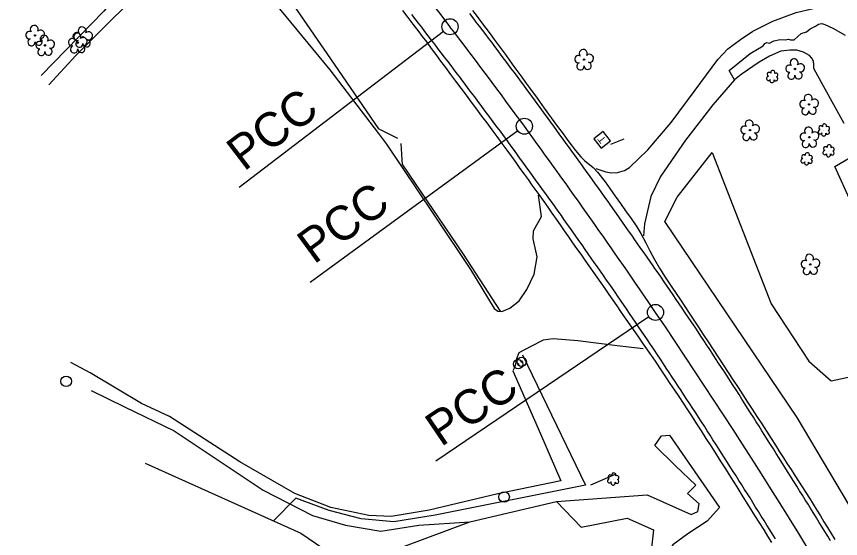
# Model space of a CAD drawing. Extents: x 474972 to 479313, y 498315 to 502691.
# Drawn here: x 477234.5 to 477618.9, y 499710.1 to 499953.8 of the extents above; entities that cross this region are included whole.
import ezdxf

# ---------------------------------------------------------------- set-up
doc = ezdxf.new("R2010")
doc.units = 0
for name, color, linetype in [('Exist Horizontal Alignment', 7, 'Continuous'), ('Exist Other Culture Fence Line', 7, 'Continuous'), ('Exist Other Culture Gate', 7, 'Continuous'), ('Exist Other Culture Sign', 7, 'Continuous'), ('Exist Roads EOP', 7, 'Continuous'), ('Exist Roads EOP Other', 7, 'Continuous'), ('Exist Roads EOT', 7, 'Continuous'), ('Exist Roads Soil', 7, 'Continuous'), ('Exist Utilities Other Located Object CELL', 7, 'Continuous'), ('Exist Utilities Other Pole CELL', 7, 'Continuous'), ('Exist Utilities Telephone Pedestal CELL', 7, 'Continuous'), ('Exist Vegetation Hedge Row', 7, 'Continuous'), ('Exist Vegetation Shrub CELL', 7, 'Continuous'), ('Exist Vegetation Tree CELL', 7, 'Continuous'), ('Exist Vegetation Woods Line', 7, 'Continuous')]:
    doc.layers.add(name, color=color, linetype=linetype)

msp = doc.modelspace()

# ---------------------------------------------------------------- linework, layer by layer
at = {"layer": 'Exist Horizontal Alignment'}
for p, q in [((477433.72, 499946.76), (477338.28, 499873.96)), ((477468.35, 499900.35), (477371.41, 499829.57)), ((477529.46, 499813.56), (477430.14, 499746.15))]:
    msp.add_line(p, q, dxfattribs=at)
for centre in [(477436.7, 499949.03), (477471.38, 499902.56), (477532.56, 499815.66)]:
    msp.add_circle(centre, 3.75, dxfattribs=at)
for centre, radius, start, end in [((475159.06, 498211.82), 2864.54, 37.33366, 48.4381), ((475236.75, 498271.08), 2766.82, 36.13278, 37.33366), ((474971.71, 498077.57), 3094.99, 34.16531, 36.13278), ((475221.34, 498247), 2793.29, 28.78535, 34.16531)]:
    msp.add_arc(centre, radius, start, end, dxfattribs=at)
at = {"layer": 'Exist Other Culture Fence Line'}
for points in [[(477252.46, 499976.08), (477320.07, 500023.97), (477331.36, 500006.71), (477363.76, 499959.01), (477380.88, 499934.01), (477403.42, 499901.35)], [(477414.47, 499884.47), (477442.82, 499842.83), (477460.07, 499816.31)], [(477470.47, 499795.88), (477499.9, 499734.95), (477429.75, 499721.06), (477410.53, 499717.94), (477395.31, 499719.29), (477380.34, 499723.11), (477364.85, 499728.91), (477354.49, 499718.55)]]:
    msp.add_lwpolyline(points, dxfattribs=at)
at = {"layer": 'Exist Other Culture Gate'}
for p, q in [((477412.43, 499896.8), (477403.42, 499901.35)), ((477414.47, 499884.47), (477413.91, 499894.54))]:
    msp.add_line(p, q, dxfattribs=at)
at = {"layer": 'Exist Other Culture Sign'}
for p, q in [((477517.81, 499896.46), (477511.5, 499894.03)), ((477502.37, 499735.15), (477513.9, 499740.16))]:
    msp.add_line(p, q, dxfattribs=at)
at = {"layer": 'Exist Roads EOP'}
for points in [[(477586.86, 499708.28), (477584.99, 499711.26), (477583.17, 499714.15), (477581.22, 499717.25), (477578.96, 499720.85), (477576.39, 499724.96), (477573.51, 499729.56), (477570.58, 499734.26), (477567.84, 499738.62), (477565.3, 499742.66), (477562.95, 499746.36), (477560.7, 499749.89), (477558.48, 499753.39), (477556.26, 499756.85), (477554.07, 499760.3), (477551.9, 499763.68), (477549.76, 499766.97), (477547.66, 499770.18), (477545.6, 499773.29), (477543.55, 499776.37), (477541.51, 499779.43), (477539.47, 499782.49), (477537.44, 499785.54), (477535.54, 499788.39), (477532.5, 499792.86), (477530.34, 499795.94), (477526.98, 499800.84), (477524.41, 499804.6), (477521.45, 499808.84), (477518.17, 499813.55), (477516.42, 499816.07), (477514.61, 499818.7), (477512.76, 499821.38), (477510.9, 499824.07), (477509.03, 499826.75), (477507.16, 499829.43), (477505.29, 499832.11), (477503.41, 499834.78), (477501.54, 499837.45), (477499.68, 499840.11), (477497.81, 499842.78), (477495.92, 499845.48), (477494.02, 499848.21), (477492.1, 499850.96), (477490.17, 499853.72), (477488.25, 499856.49), (477486.32, 499859.25), (477484.38, 499862.01), (477482.47, 499864.74), (477480.58, 499867.41), (477478.73, 499870.02), (477476.92, 499872.57), (477475.1, 499875.11), (477473.26, 499877.67), (477471.4, 499880.26), (477469.5, 499882.88), (477467.54, 499885.59), (477465.47, 499888.43), (477463.31, 499891.41), (477461.04, 499894.54), (477458.71, 499897.73), (477456.36, 499900.93), (477454, 499904.13), (477451.62, 499907.33), (477449.22, 499910.54), (477446.8, 499913.77), (477444.36, 499917.03), (477441.89, 499920.32), (477439.45, 499923.58), (477437.07, 499926.78), (477434.75, 499929.92), (477432.49, 499933), (477430.28, 499936), (477428.12, 499938.92), (477425.99, 499941.76), (477423.9, 499944.52), (477421.78, 499947.3), (477419.53, 499950.23), (477417.16, 499953.31), (477414.67, 499956.52)], [(477447.24, 499956.62), (477449.38, 499953.78), (477451.45, 499951.01), (477453.44, 499948.33), (477455.39, 499945.71), (477457.3, 499943.12), (477459.17, 499940.57), (477461.01, 499938.04), (477462.84, 499935.53), (477464.67, 499933.02), (477466.5, 499930.5), (477468.33, 499927.97), (477470.16, 499925.46), (477471.97, 499922.98), (477473.77, 499920.52), (477477.29, 499915.69), (477480.7, 499910.98), (477483.96, 499906.44), (477486.89, 499902.41), (477489.47, 499898.94), (477491.73, 499895.94), (477495.29, 499891.29), (477497.67, 499888.34), (477499.41, 499886.5), (477503.49, 499883.23), (477505.48, 499881.19), (477509.04, 499876.68), (477511.3, 499873.54), (477513.77, 499869.96), (477516.21, 499866.47), (477518.62, 499863.09), (477521.19, 499859.43), (477523.84, 499855.56), (477525.78, 499852.45), (477527.99, 499848.15), (477529.92, 499844.42), (477532.04, 499840.38), (477534.42, 499836.24), (477537.05, 499832.18), (477540.24, 499827.39), (477542.17, 499824.5), (477544.15, 499821.53), (477546.19, 499818.46), (477548.29, 499815.32), (477550.43, 499812.08), (477552.62, 499808.76), (477554.87, 499805.34), (477557.15, 499801.84), (477559.47, 499798.29), (477561.8, 499794.73), (477564.14, 499791.17), (477566.49, 499787.6), (477568.82, 499784.06), (477571.1, 499780.58), (477573.34, 499777.15), (477575.53, 499773.78), (477577.71, 499770.42), (477579.9, 499767.03), (477582.1, 499763.61), (477584.31, 499760.17), (477586.48, 499756.8), (477588.53, 499753.6), (477590.46, 499750.58), (477592.29, 499747.74), (477594.04, 499744.99), (477595.78, 499742.28), (477597.51, 499739.59), (477599.22, 499736.92), (477600.92, 499734.26), (477602.63, 499731.57), (477604.34, 499728.86), (477606.06, 499726.13), (477607.77, 499723.38), (477609.46, 499720.65), (477611.13, 499717.92), (477612.79, 499715.2), (477614.46, 499712.45), (477616.18, 499709.63)]]:
    msp.add_lwpolyline(points, dxfattribs=at)
at = {"layer": 'Exist Roads EOP Other'}
for points in [[(477620.56, 499903.88), (477611, 499921.25), (477606.36, 499929.49), (477606.41, 499931.2), (477606.25, 499932.98), (477605.51, 499934.39), (477604.46, 499935.51), (477601.65, 499937.12), (477598.41, 499938.06), (477595.23, 499938.13), (477591.05, 499937.62), (477585.71, 499935.21), (477580.96, 499932.41), (477572.48, 499926.7), (477569.34, 499924.21), (477566.9, 499928.64), (477576.74, 499936.48), (477582.82, 499940.05), (477583.57, 499941.25), (477584.55, 499941.7), (477585.79, 499941.35), (477587.79, 499942.39), (477590.78, 499943.08), (477593.09, 499942.85), (477594.55, 499943.21), (477595.57, 499942.83), (477597.2, 499942.85), (477598.93, 499944.46), (477600.52, 499945.81), (477603.01, 499946.64), (477604.78, 499948.04), (477607.27, 499949.32), (477608.65, 499950.18), (477610.17, 499950.53), (477611.61, 499950.08), (477615.29, 499948.29), (477620.99, 499945.06)], [(477623.82, 499866.98), (477616.17, 499883.71), (477627.93, 499890.55)]]:
    msp.add_lwpolyline(points, dxfattribs=at)
at = {"layer": 'Exist Roads EOT'}
for points in [[(477614.25, 499709.07), (477612.93, 499711.2), (477611.61, 499713.32), (477610.29, 499715.44), (477608.98, 499717.57), (477607.66, 499719.69), (477606.34, 499721.81), (477605.02, 499723.94), (477603.71, 499726.06), (477602.39, 499728.18), (477601.07, 499730.3), (477599.75, 499732.43), (477598.43, 499734.55), (477597.12, 499736.67), (477596.85, 499737.11), (477595.52, 499739.22), (477594.19, 499741.34), (477592.85, 499743.45), (477591.52, 499745.56), (477590.19, 499747.68), (477588.86, 499749.79), (477587.53, 499751.91), (477586.2, 499754.02), (477584.87, 499756.14), (477583.54, 499758.25), (477582.21, 499760.37), (477580.87, 499762.48), (477579.54, 499764.6), (477578.21, 499766.71), (477576.88, 499768.83), (477575.55, 499770.94), (477574.22, 499773.05), (477572.89, 499775.17), (477571.56, 499777.28), (477570.17, 499779.48), (477568.81, 499781.57), (477567.44, 499783.66), (477566.07, 499785.75), (477564.7, 499787.84), (477563.33, 499789.93), (477561.97, 499792.02), (477560.6, 499794.11), (477559.23, 499796.21), (477557.86, 499798.3), (477556.49, 499800.39), (477555.13, 499802.48), (477553.76, 499804.57), (477552.39, 499806.66), (477551.02, 499808.75), (477550.64, 499809.34), (477549.23, 499811.4), (477547.82, 499813.47), (477546.41, 499815.53), (477545, 499817.59), (477543.59, 499819.66), (477542.18, 499821.72), (477540.77, 499823.78), (477539.36, 499825.85), (477537.95, 499827.91), (477536.54, 499829.97), (477535.14, 499832.04), (477533.73, 499834.1), (477532.32, 499836.16), (477531.51, 499837.34), (477530.08, 499839.38), (477528.64, 499841.43), (477527.21, 499843.48), (477525.77, 499845.52), (477524.34, 499847.57), (477522.9, 499849.61), (477521.47, 499851.66), (477520.03, 499853.7), (477518.6, 499855.75), (477517.16, 499857.8), (477515.73, 499859.84), (477514.29, 499861.89), (477512.86, 499863.93), (477511.42, 499865.98), (477510.44, 499867.38), (477508.99, 499869.41), (477507.53, 499871.44), (477506.08, 499873.48), (477504.62, 499875.51), (477503.17, 499877.54), (477501.72, 499879.57), (477500.26, 499881.6), (477498.81, 499883.64), (477497.35, 499885.67), (477496.8, 499886.44), (477495.34, 499888.46), (477493.87, 499890.49), (477492.4, 499892.51), (477490.93, 499894.53), (477489.47, 499896.55), (477488, 499898.58), (477486.53, 499900.6), (477485.06, 499902.62), (477483.6, 499904.64), (477482.13, 499906.67), (477480.66, 499908.69), (477479.2, 499910.71), (477477.73, 499912.73), (477476.26, 499914.76), (477474.79, 499916.78), (477474.11, 499917.73), (477472.61, 499919.73), (477471.11, 499921.73), (477469.62, 499923.73), (477468.12, 499925.73), (477466.63, 499927.74), (477465.13, 499929.74), (477463.63, 499931.74), (477462.14, 499933.74), (477460.64, 499935.74), (477459.15, 499937.74), (477457.65, 499939.75), (477456.15, 499941.75), (477454.66, 499943.75), (477453.52, 499945.27), (477452, 499947.25), (477450.48, 499949.23), (477448.96, 499951.22), (477447.44, 499953.2), (477445.92, 499955.18)], [(477588.52, 499709.95), (477587.2, 499712.08), (477585.88, 499714.2), (477584.56, 499716.32), (477583.24, 499718.44), (477581.92, 499720.56), (477580.6, 499722.69), (477579.28, 499724.81), (477577.96, 499726.93), (477576.64, 499729.05), (477575.48, 499730.91), (477574.13, 499733.02), (477572.79, 499735.13), (477571.45, 499737.24), (477570.11, 499739.34), (477568.76, 499741.45), (477567.42, 499743.56), (477566.08, 499745.66), (477564.74, 499747.77), (477563.39, 499749.88), (477562.05, 499751.99), (477560.71, 499754.09), (477559.37, 499756.2), (477558.02, 499758.31), (477556.68, 499760.42), (477555.34, 499762.52), (477554, 499764.63), (477552.65, 499766.74), (477551.36, 499768.77), (477549.98, 499770.86), (477548.6, 499772.94), (477547.23, 499775.03), (477545.85, 499777.12), (477544.48, 499779.2), (477543.1, 499781.29), (477541.73, 499783.37), (477540.35, 499785.46), (477538.98, 499787.55), (477537.6, 499789.63), (477536.23, 499791.72), (477534.85, 499793.81), (477533.47, 499795.89), (477532.1, 499797.98), (477530.72, 499800.06), (477530.29, 499800.72), (477528.89, 499802.79), (477527.48, 499804.86), (477526.08, 499806.92), (477524.68, 499808.99), (477523.27, 499811.06), (477521.87, 499813.13), (477520.47, 499815.19), (477519.06, 499817.26), (477517.66, 499819.33), (477516.26, 499821.4), (477514.86, 499823.46), (477514.07, 499824.63), (477512.63, 499826.67), (477511.2, 499828.72), (477509.76, 499830.77), (477508.33, 499832.81), (477506.89, 499834.86), (477505.46, 499836.9), (477504.02, 499838.95), (477502.59, 499840.99), (477501.15, 499843.04), (477499.72, 499845.08), (477498.28, 499847.13), (477496.85, 499849.18), (477495.41, 499851.22), (477493.98, 499853.27), (477492.54, 499855.31), (477491.11, 499857.36), (477489.67, 499859.4), (477488.67, 499860.83), (477487.21, 499862.86), (477485.75, 499864.88), (477484.29, 499866.91), (477482.82, 499868.94), (477481.36, 499870.96), (477479.9, 499872.99), (477478.44, 499875.02), (477476.97, 499877.04), (477475.51, 499879.07), (477474.05, 499881.09), (477472.59, 499883.12), (477471.12, 499885.15), (477469.66, 499887.17), (477468.2, 499889.2), (477466.74, 499891.22), (477465.28, 499893.25), (477463.81, 499895.28), (477463.16, 499896.18), (477461.67, 499898.18), (477460.18, 499900.19), (477458.68, 499902.19), (477457.19, 499904.2), (477455.7, 499906.2), (477454.2, 499908.2), (477452.71, 499910.21), (477451.22, 499912.21), (477449.73, 499914.22), (477448.23, 499916.22), (477446.74, 499918.23), (477445.25, 499920.23), (477443.76, 499922.23), (477442.26, 499924.24), (477441.73, 499924.95), (477440.22, 499926.93), (477438.7, 499928.92), (477437.18, 499930.9), (477435.66, 499932.89), (477434.14, 499934.87), (477432.62, 499936.85), (477431.1, 499938.84), (477429.58, 499940.82), (477428.06, 499942.81), (477426.55, 499944.79), (477425.03, 499946.78), (477423.51, 499948.76), (477421.99, 499950.75), (477420.47, 499952.73), (477418.95, 499954.71)]]:
    msp.add_lwpolyline(points, dxfattribs=at)
at = {"layer": 'Exist Roads Soil'}
for points in [[(477249.62, 499921.96), (477262.17, 499935.56), (477279.78, 499953.17), (477303.19, 499975.71)], [(477504.78, 499882.84), (477509.45, 499881.22), (477512.11, 499880.8), (477514.86, 499880.99), (477518.08, 499881.87), (477520.43, 499883.31), (477529.01, 499891.53), (477539.8, 499904.23), (477550.99, 499919.4), (477561.69, 499933.75), (477566.25, 499938.7), (477572.16, 499943.07), (477577.93, 499946.92), (477587.31, 499951.56), (477598.24, 499955.69), (477611.38, 499958.83), (477624.47, 499963.13)], [(477357.18, 499957.4), (477380.64, 499928.89), (477403.36, 499899.13), (477407.15, 499894.16), (477428.99, 499861.48), (477446.2, 499835.73), (477457.32, 499817.51), (477458.98, 499816.25), (477460.84, 499816.09), (477464.58, 499817.7), (477469.02, 499821.08), (477472.47, 499826.3), (477476.03, 499833.56), (477477.4, 499841.67), (477475.46, 499850.03), (477475.69, 499853.66), (477479.45, 499860.46), (477478.02, 499870.32)], [(477569.34, 499924.21), (477559.28, 499912.59), (477546.59, 499896.07), (477534.82, 499879.07), (477530.31, 499869.74), (477528.75, 499863.06), (477527.38, 499857), (477526.95, 499851.47)], [(477526.81, 499798.65), (477514.6, 499800.11), (477496.31, 499802.44), (477484.81, 499803.26), (477480.11, 499802.72), (477474.34, 499799.67), (477468.8, 499796.74), (477467.67, 499793.95), (477466.93, 499790.31), (477465.94, 499788.4), (477478.99, 499758.96), (477488.35, 499737.05), (477459.01, 499730.95), (477426.96, 499723.28), (477409.24, 499720.34), (477398.88, 499720.79), (477381.08, 499724.55), (477364.34, 499731.09), (477338.68, 499745.94), (477305.81, 499767.03), (477292.77, 499773.1), (477268.8, 499787.48), (477259.76, 499792.2)]]:
    msp.add_lwpolyline(points, dxfattribs=at)
at = {"layer": 'Exist Utilities Other Located Object CELL'}
for centre, radius in [((477468.45, 499791.53), 2.18), ((477470.14, 499792.61), 2.18), ((477468.45, 499791.53), 0.24), ((477470.14, 499792.61), 0.24)]:
    msp.add_circle(centre, radius, dxfattribs=at)
at = {"layer": 'Exist Utilities Other Pole CELL'}
for centre in [(477257.65, 499783.48), (477461.94, 499729.48)]:
    msp.add_circle(centre, 2.46, dxfattribs=at)
at = {"layer": 'Exist Utilities Telephone Pedestal CELL'}
msp.add_line((477507.71, 499896.13), (477507.71, 499896.13), dxfattribs=at)
msp.add_lwpolyline([(477511.62, 499895.71), (477508.19, 499900.13), (477503.77, 499896.7), (477507.2, 499892.28), (477511.62, 499895.71)], dxfattribs=at)
at = {"layer": 'Exist Vegetation Hedge Row'}
for points in [[(477320.82, 500031.77), (477317.76, 500016.55), (477311.47, 500002.27), (477298.41, 499983.94), (477275.15, 499956.26), (477245.99, 499926.25)], [(477269.37, 499779.25), (477284.86, 499771.54), (477308.07, 499760.36), (477349.61, 499732.64), (477372.5, 499720.85), (477387.95, 499716.27), (477404.4, 499713.6), (477422.11, 499716.34), (477445.96, 499717.86)], [(477486.39, 499727.41), (477528.65, 499730.51), (477549.21, 499721.35), (477552.29, 499722.77), (477553, 499726.28), (477547.48, 499731.19), (477551.33, 499735.05), (477541.81, 499744.09), (477532.17, 499753.56), (477535.3, 499758.1), (477539.02, 499758.42), (477562.43, 499724.59), (477556.72, 499718.25), (477547.71, 499712.36), (477540.58, 499707.1), (477528.83, 499688.95)]]:
    msp.add_lwpolyline(points, dxfattribs=at)
at = {"layer": 'Exist Vegetation Shrub CELL'}
for p, q in [((477587.05, 499925.6), (477587.05, 499925.6)), ((477611.15, 499900.64), (477611.15, 499900.64)), ((477613.36, 499890.93), (477613.36, 499890.93)), ((477603.14, 499887.15), (477603.14, 499887.15)), ((477512.9, 499737.69), (477512.9, 499737.69))]:
    msp.add_line(p, q, dxfattribs=at)
for centre, radius, start, end in [((477587.28, 499927.64), 0.99, 334.8391, 200.4717), ((477585.25, 499924.89), 0.955, 95.1099, 327.9534), ((477585.57, 499926.72), 0.968, 35.8908, 245.4216), ((477586.92, 499923.91), 0.984, 151.2797, 21.387), ((477588.69, 499924.67), 0.937, 204.9913, 73.4601), ((477588.72, 499926.47), 0.929, 284.4567, 126.0861), ((477609.67, 499901.77), 0.968, 35.8908, 245.4216), ((477611.38, 499902.68), 0.99, 334.8391, 200.4717), ((477612.82, 499901.51), 0.929, 284.4567, 126.0861), ((477609.35, 499899.94), 0.955, 95.1099, 327.9534), ((477611.02, 499898.96), 0.984, 151.2797, 21.387), ((477612.79, 499899.71), 0.937, 204.9913, 73.4601), ((477613.58, 499892.97), 0.99, 334.8391, 200.4717), ((477603.37, 499889.19), 0.99, 334.8391, 200.4717), ((477611.56, 499890.23), 0.955, 95.1099, 327.9534), ((477611.87, 499892.06), 0.968, 35.8908, 245.4216), ((477613.23, 499889.25), 0.984, 151.2797, 21.387), ((477614.99, 499890), 0.937, 204.9913, 73.4601), ((477615.03, 499891.8), 0.929, 284.4567, 126.0861), ((477601.34, 499886.45), 0.955, 95.1099, 327.9534), ((477601.66, 499888.28), 0.968, 35.8908, 245.4216), ((477603.01, 499885.47), 0.984, 151.2797, 21.387), ((477604.78, 499886.23), 0.937, 204.9913, 73.4601), ((477604.81, 499888.02), 0.929, 284.4567, 126.0861), ((477511.42, 499738.82), 0.968, 35.8908, 245.4216), ((477513.13, 499739.73), 0.99, 334.8391, 200.4717), ((477511.1, 499736.99), 0.955, 95.1099, 327.9534), ((477512.77, 499736.01), 0.984, 151.2797, 21.387), ((477514.54, 499736.77), 0.937, 204.9913, 73.4601), ((477514.57, 499738.56), 0.929, 284.4567, 126.0861)]:
    msp.add_arc(centre, radius, start, end, dxfattribs=at)
at = {"layer": 'Exist Vegetation Tree CELL'}
for p, q in [((477243.17, 499944.93), (477243.17, 499944.93)), ((477265.52, 499944.19), (477265.52, 499944.19)), ((477247.76, 499940.32), (477247.76, 499940.32)), ((477263.05, 499941.58), (477263.05, 499941.58)), ((477499.25, 499933.66), (477499.25, 499933.66)), ((477597.62, 499929.29), (477597.62, 499929.29)), ((477604.18, 499912.72), (477604.18, 499912.72)), ((477576.63, 499900.74), (477576.63, 499900.74)), ((477604.33, 499897.43), (477604.33, 499897.43)), ((477604.76, 499838.07), (477604.76, 499838.07))]:
    msp.add_line(p, q, dxfattribs=at)
for centre in [(477243.17, 499944.93), (477265.52, 499944.19), (477247.76, 499940.32), (477263.05, 499941.58), (477499.25, 499933.66), (477597.62, 499929.29), (477604.18, 499912.72), (477576.63, 499900.74), (477604.33, 499897.43), (477604.76, 499838.07)]:
    msp.add_circle(centre, 0.326, dxfattribs=at)
for centre, radius, start, end in [((477242.78, 499947.8), 1.86, 330.1651, 219.7134), ((477245.72, 499945.52), 1.9, 257.1011, 134.1999), ((477265.14, 499947.06), 1.86, 330.1651, 219.7134), ((477240.56, 499945.08), 1.73, 62.6636, 279.3457), ((477244.84, 499942.03), 1.7, 181.2822, 74.56), ((477247.37, 499943.2), 1.86, 330.1651, 219.7134), ((477260.45, 499941.74), 1.73, 62.6636, 279.3457), ((477262.67, 499944.46), 1.86, 330.1651, 219.7134), ((477262.92, 499944.34), 1.73, 62.6636, 279.3457), ((477265.6, 499942.17), 1.9, 257.1011, 134.1999), ((477268.07, 499944.77), 1.9, 257.1011, 134.1999), ((477241.47, 499941.81), 1.69, 111.5671, 6.231), ((477245.15, 499940.48), 1.73, 62.6636, 279.3457), ((477250.31, 499940.91), 1.9, 257.1011, 134.1999), ((477261.35, 499938.46), 1.69, 111.5671, 6.231), ((477263.82, 499941.07), 1.69, 111.5671, 6.231), ((477264.73, 499938.68), 1.7, 181.2822, 74.56), ((477267.2, 499941.29), 1.7, 181.2822, 74.56), ((477246.06, 499937.2), 1.69, 111.5671, 6.231), ((477249.43, 499937.42), 1.7, 181.2822, 74.56), ((477498.87, 499936.54), 1.86, 330.1651, 219.7134), ((477501.8, 499934.25), 1.9, 257.1011, 134.1999), ((477496.64, 499933.82), 1.73, 62.6636, 279.3457), ((477497.55, 499930.54), 1.69, 111.5671, 6.231), ((477500.92, 499930.76), 1.7, 181.2822, 74.56), ((477597.23, 499932.16), 1.86, 330.1651, 219.7134), ((477595.01, 499929.44), 1.73, 62.6636, 279.3457), ((477600.17, 499929.87), 1.9, 257.1011, 134.1999), ((477595.91, 499926.16), 1.69, 111.5671, 6.231), ((477599.29, 499926.39), 1.7, 181.2822, 74.56), ((477603.79, 499915.59), 1.86, 330.1651, 219.7134), ((477601.57, 499912.88), 1.73, 62.6636, 279.3457), ((477606.73, 499913.31), 1.9, 257.1011, 134.1999), ((477602.47, 499909.6), 1.69, 111.5671, 6.231), ((477605.85, 499909.82), 1.7, 181.2822, 74.56), ((477576.24, 499903.61), 1.86, 330.1651, 219.7134), ((477574.02, 499900.9), 1.73, 62.6636, 279.3457), ((477579.18, 499901.33), 1.9, 257.1011, 134.1999), ((477603.95, 499900.3), 1.86, 330.1651, 219.7134), ((477574.93, 499897.62), 1.69, 111.5671, 6.231), ((477578.3, 499897.84), 1.7, 181.2822, 74.56), ((477601.73, 499897.58), 1.73, 62.6636, 279.3457), ((477606.88, 499898.02), 1.9, 257.1011, 134.1999), ((477602.63, 499894.31), 1.69, 111.5671, 6.231), ((477606.01, 499894.53), 1.7, 181.2822, 74.56), ((477602.15, 499838.22), 1.73, 62.6636, 279.3457), ((477604.37, 499840.94), 1.86, 330.1651, 219.7134), ((477607.31, 499838.66), 1.9, 257.1011, 134.1999), ((477603.05, 499834.95), 1.69, 111.5671, 6.231), ((477606.43, 499835.17), 1.7, 181.2822, 74.56)]:
    msp.add_arc(centre, radius, start, end, dxfattribs=at)
at = {"layer": 'Exist Vegetation Woods Line'}
for points in [[(477652.36, 499676.12), (477598.61, 499766.54), (477536.87, 499858.1), (477542.59, 499869.49), (477558.92, 499890.34), (477586.48, 499819.67), (477604.15, 499792.83), (477614.53, 499783.71), (477639.07, 499788.98), (477674.86, 499796.46), (477692.31, 499767.47), (477709.96, 499750.14), (477688.89, 499730.68), (477711.45, 499683.2)], [(477294.53, 499745.32), (477303.88, 499741.02), (477367.19, 499712.58), (477391.01, 499696.27), (477407.23, 499697.03), (477414.69, 499706.21), (477445.96, 499717.86), (477486.39, 499727.41), (477497.87, 499715.45), (477519.3, 499719.61), (477531.6, 499714.1), (477528.83, 499688.95), (477482.76, 499677.67), (477474.42, 499679.82), (477416.92, 499643.11), (477411.1, 499634.09), (477411.07, 499620.55)]]:
    msp.add_lwpolyline(points, dxfattribs=at)

# ---------------------------------------------------------------- texts
at = {"layer": 'Exist Horizontal Alignment'}
for rotation, p in [(37.3337, (477340.58, 499881.22)), (36.1328, (477373.23, 499837.83)), (34.1653, (477432.47, 499752.6))]:
    msp.add_text('PCC', height=16, rotation=rotation, dxfattribs=at).set_placement(p)
at = {"layer": 'Exist Utilities Telephone Pedestal CELL'}
msp.add_text('T', height=3.42, rotation=127.8163, dxfattribs=at).set_placement((477509.76, 499896.29))

doc.saveas('drawing.dxf')
